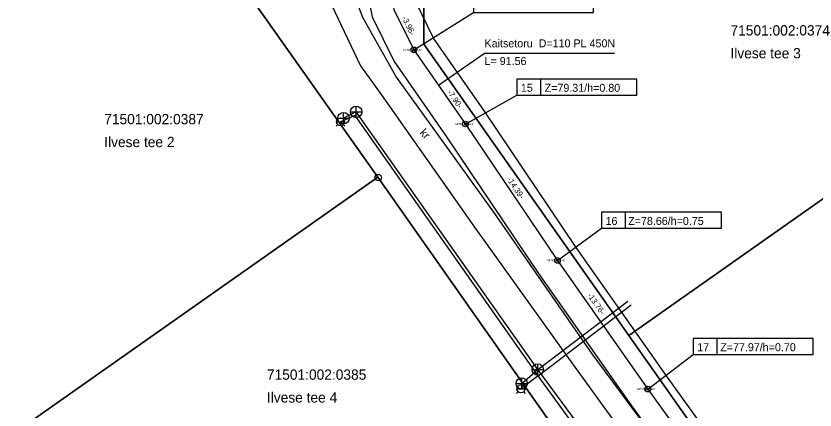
# Model space of a CAD drawing. Extents: x 593727 to 603084, y 6472047 to 6482364.
# Drawn here: x 595964.2 to 596034.1, y 6474006.5 to 6474041 of the extents above; entities that cross this region are included whole.
import ezdxf

# ---------------------------------------------------------------- set-up
doc = ezdxf.new("R2010")
doc.units = 0
for name, color, linetype in [('JOONSIDE', 7, 'Continuous'), ('KKAEV', 7, 'Continuous'), ('KOORDPUNKT', 7, 'Continuous'), ('KTRASS', 7, 'Continuous'), ('MOOTKORG-EH2000', 7, 'Continuous'), ('MOOTMPUNKT', 7, 'Continuous'), ('MOOTNR', 7, 'Continuous'), ('MOOTPIIR', 7, 'Continuous'), ('MPKAABEL', 7, 'Continuous'), ('PIIR', 7, 'Continuous'), ('PIIRIMLEITUD', 7, 'Continuous'), ('TEE', 7, 'Continuous'), ('VKAEV', 7, 'Continuous'), ('VTRASS', 7, 'Continuous')]:
    doc.layers.add(name, color=color, linetype=linetype)

msp = doc.modelspace()

# ---------------------------------------------------------------- linework, layer by layer
at = {"layer": 'KKAEV'}
for p, q in [((595993.91, 6474032.084), (595993.91, 6474033.084)), ((595992.815, 6474031.528), (595992.815, 6474032.528)), ((595993.41, 6474032.584), (595994.41, 6474032.584)), ((595992.315, 6474032.028), (595993.315, 6474032.028)), ((596009.3, 6474010.035), (596010.3, 6474010.035)), ((596009.8, 6474009.535), (596009.8, 6474010.535)), ((596008.4, 6474008.316), (596008.4, 6474009.316)), ((596007.9, 6474008.816), (596008.9, 6474008.816))]:
    msp.add_line(p, q, dxfattribs=at)
for centre in [(595993.91, 6474032.584), (595992.815, 6474032.028), (596009.8, 6474010.035), (596008.4, 6474008.816)]:
    msp.add_circle(centre, 0.5, dxfattribs=at)
at = {"layer": 'KOORDPUNKT'}
for points in [[(595998.968, 6474037.996), (596004.171, 6474041.262), (596014.671, 6474041.262), (596014.671, 6474042.662), (596004.171, 6474042.662), (596004.171, 6474041.262)], [(596003.482, 6474031.514), (596007.973, 6474034.053), (596018.473, 6474034.053), (596018.473, 6474035.453), (596007.973, 6474035.453), (596007.973, 6474034.053)], [(596010.073, 6474034.053), (596010.073, 6474035.453)], [(596011.528, 6474019.578), (596015.367, 6474022.4), (596025.867, 6474022.4), (596025.867, 6474023.8), (596015.367, 6474023.8), (596015.367, 6474022.4)], [(596017.467, 6474022.4), (596017.467, 6474023.8)], [(596019.439, 6474008.315), (596023.402, 6474011.354), (596033.902, 6474011.354), (596033.902, 6474012.754), (596023.402, 6474012.754), (596023.402, 6474011.354)], [(596025.502, 6474011.354), (596025.502, 6474012.754)]]:
    msp.add_lwpolyline(points, dxfattribs=at)
for centre, radius in [((595998.968, 6474037.996), 0.25), ((595998.968, 6474037.996), 0.025), ((595998.968, 6474037.996), 0.0221), ((595998.968, 6474037.996), 0.0191), ((595998.968, 6474037.996), 0.0161), ((595998.968, 6474037.996), 0.0132), ((595998.968, 6474037.996), 0.0102), ((595998.968, 6474037.996), 0.00726), ((595998.968, 6474037.996), 0.0043), ((596003.482, 6474031.514), 0.25), ((596003.482, 6474031.514), 0.025), ((596003.482, 6474031.514), 0.0221), ((596003.482, 6474031.514), 0.0191), ((596003.482, 6474031.514), 0.0161), ((596003.482, 6474031.514), 0.0132), ((596003.482, 6474031.514), 0.0102), ((596003.482, 6474031.514), 0.00726), ((596003.482, 6474031.514), 0.0043), ((596011.528, 6474019.578), 0.25), ((596011.528, 6474019.578), 0.025), ((596011.528, 6474019.578), 0.0221), ((596011.528, 6474019.578), 0.0191), ((596011.528, 6474019.578), 0.0161), ((596011.528, 6474019.578), 0.0132), ((596011.528, 6474019.578), 0.0102), ((596011.528, 6474019.578), 0.00726), ((596011.528, 6474019.578), 0.0043), ((596019.439, 6474008.315), 0.25), ((596019.439, 6474008.315), 0.025), ((596019.439, 6474008.315), 0.0221), ((596019.439, 6474008.315), 0.0191), ((596019.439, 6474008.315), 0.0161), ((596019.439, 6474008.315), 0.0132), ((596019.439, 6474008.315), 0.0102), ((596019.439, 6474008.315), 0.00726), ((596019.439, 6474008.315), 0.0043)]:
    msp.add_circle(centre, radius, dxfattribs=at)
at = {"layer": 'KTRASS'}
for p, q in [((596009.8, 6474010.035), (596017.69, 6474016.021)), ((596008.4, 6474008.816), (596009.8, 6474010.035))]:
    msp.add_line(p, q, dxfattribs=at)
msp.add_lwpolyline([(596021.268, 6473994.477), (596009.8, 6474010.035), (595993.91, 6474032.584), (595992.815, 6474032.028)], dxfattribs=at)
at = {"layer": 'MOOTMPUNKT'}
for centre in [(595998.968, 6474037.996), (596003.482, 6474031.514), (596011.528, 6474019.578), (596019.439, 6474008.315)]:
    msp.add_circle(centre, 0.1, dxfattribs=at)
at = {"layer": 'MOOTPIIR'}
for points in [[(595994.372, 6474045.491), (595995.314, 6474040.897), (595997.24, 6474036.978), (596001.832, 6474030.384), (596009.88, 6474018.444), (596017.808, 6474007.157), (596025.372, 6473996.624)], [(596028.584, 6473999.008), (596021.07, 6474009.473), (596013.176, 6474020.712), (596005.132, 6474032.644), (596000.696, 6474039.014), (595999.13, 6474042.201)]]:
    msp.add_lwpolyline(points, dxfattribs=at)
at = {"layer": 'MPKAABEL'}
for points in [[(596014.463, 6474066.806), (596002.148, 6474057.419), (595998.723, 6474054.604), (595996.671, 6474051.87), (595996.141, 6474049.764), (595996.361, 6474045.748), (595997.222, 6474041.549), (595998.968, 6474037.996), (596003.482, 6474031.514), (596011.528, 6474019.578), (596019.439, 6474008.315), (596026.978, 6473997.816), (596029.342, 6473994.732), (596029.364, 6473993.819)], [(595997.222, 6474041.549), (595998.968, 6474037.996), (596003.482, 6474031.514), (596011.528, 6474019.578), (596019.439, 6474008.315), (596026.978, 6473997.816), (596029.342, 6473994.732), (596029.364, 6473993.819), (596026.896, 6473991.824), (596022.401, 6473988.312), (596009.78, 6473979.811), (596004.261, 6473975.645), (595998.04, 6473970.949), (595995.228, 6473969.033), (595993.808, 6473968.997), (595992.272, 6473970.526), (595991.471, 6473971.588), (595989.417, 6473974.773), (595989.197, 6473975.301)], [(596001.113, 6474034.915), (596005.148, 6474037.725), (596016.522, 6474037.725)]]:
    msp.add_lwpolyline(points, dxfattribs=at)
at = {"layer": 'PIIR'}
for points in [[(596017.77, 6474013.02), (595999.85, 6474038.49), (595999.81, 6474054.43), (596023.26, 6474070.93), (596048.7, 6474034.81)], [(595920.02, 6474021.81), (595923.45, 6474023.94), (595974.94, 6474056.4), (595995.81, 6474026.85), (595965.97, 6474005.85), (595935.81, 6473984.63), (595931.46, 6473994.7)], [(596017.77, 6474013.02), (596048.7, 6474034.81), (596055.18, 6474039.36), (596075.89, 6474009.92), (596066.09, 6474003.01), (596067.53, 6474000.96), (596039.91, 6473981.55)], [(595965.97, 6474005.85), (595995.81, 6474026.85), (596019.09, 6473993.75), (595999.1, 6473979.65), (595997.67, 6473981.68), (595987.85, 6473974.77)]]:
    msp.add_lwpolyline(points, close=True, dxfattribs=at)
for points in [[(596066.57, 6473926.31), (596046.52, 6473955.01), (596023.13, 6473988.02), (596003.14, 6473973.91), (596004.56, 6473971.88), (595994.75, 6473964.97), (595991.31, 6473969.86), (595987.85, 6473974.77), (595997.67, 6473981.68), (595999.1, 6473979.65), (596019.09, 6473993.75), (595995.81, 6474026.85), (595974.94, 6474056.4)], [(595999.81, 6474054.43), (595999.85, 6474038.49), (596017.77, 6474013.02), (596039.91, 6473981.55), (596067.53, 6474000.96), (596066.09, 6474003.01), (596075.89, 6474009.92), (596079.35, 6474005.02), (596082.79, 6474000.11), (596072.98, 6473993.2), (596071.55, 6473995.25), (596043.93, 6473975.83), (596066.1, 6473944.35)]]:
    msp.add_lwpolyline(points, dxfattribs=at)
at = {"layer": 'PIIRIMLEITUD'}
msp.add_circle((595995.847, 6474026.821), 0.285, dxfattribs=at)
at = {"layer": 'TEE'}
for points in [[(596031.92, 6474089.538), (596031.304, 6474086.654), (596029.381, 6474083.691), (596025.099, 6474079.23), (596019.083, 6474074.682), (596007.86, 6474067.339), (595996.337, 6474059.544), (595994.689, 6474057.913), (595992.598, 6474055.095), (595991.286, 6474052.246), (595990.709, 6474049.521), (595990.678, 6474045.813), (595991.744, 6474041.996), (595994.295, 6474036.613), (595996.116, 6474034.095), (596004.269, 6474022.484), (596012.454, 6474011.067), (596021.171, 6473999.009), (596029.659, 6473987.552)], [(596031.256, 6473989.002), (596022.629, 6474000.49), (596014.566, 6474011.418), (596005.949, 6474023.815), (595997.389, 6474035.698), (595994.514, 6474040.842), (595992.998, 6474044.834), (595992.861, 6474048.906), (595993.607, 6474052.227), (595995.052, 6474054.981), (595997.577, 6474057.706), (596008.43, 6474065.294), (596020.365, 6474072.528), (596025.712, 6474076.969), (596031.411, 6474082.45), (596033.754, 6474085.703), (596034.258, 6474088.185)]]:
    msp.add_lwpolyline(points, dxfattribs=at)
at = {"layer": 'VKAEV'}
for p, q in [((595992.197, 6474031.717), (595992.897, 6474031.717)), ((595992.3, 6474031.47), (595992.16, 6474031.33)), ((595992.794, 6474031.47), (595992.934, 6474031.33)), ((596008.079, 6474008.083), (596007.939, 6474007.943)), ((596007.976, 6474008.33), (596008.676, 6474008.33)), ((596008.573, 6474008.083), (596008.713, 6474007.943))]:
    msp.add_line(p, q, dxfattribs=at)
for centre in [(595992.547, 6474031.717), (596008.326, 6474008.33)]:
    msp.add_circle(centre, 0.35, dxfattribs=at)
at = {"layer": 'VTRASS'}
msp.add_line((596009.847, 6474009.478), (596017.976, 6474015.699), dxfattribs=at)
for points in [[(596009.847, 6474009.478), (595993.822, 6474032.26), (595992.547, 6474031.717)], [(596021.07, 6473993.982), (596009.847, 6474009.478), (596008.326, 6474008.33)]]:
    msp.add_lwpolyline(points, dxfattribs=at)

# ---------------------------------------------------------------- texts
at = {"layer": 'JOONSIDE'}
for s, rotation, p in [('-3.96-', 296.17023, (595997.901, 6474040.791)), ('-7.90-', 304.85297, (596001.865, 6474034.277)), ('-14.39-', 303.98372, (596007.076, 6474026.674)), ('-13.76-', 305.08376, (596014.115, 6474016.516))]:
    msp.add_text(s, height=0.5, rotation=rotation, dxfattribs=at).set_placement(p)
at = {"layer": 'KOORDPUNKT'}
for s, p in [('15', (596008.323, 6474034.333)), ('Z=79.31/h=0.80', (596010.406, 6474034.333)), ('16', (596015.735, 6474022.68)), ('Z=78.66/h=0.75', (596017.713, 6474022.68)), ('17', (596023.752, 6474011.634)), ('Z=77.97/h=0.70', (596025.765, 6474011.634))]:
    msp.add_text(s, height=0.7, dxfattribs=at).set_placement(p)
at = {"layer": 'MOOTKORG-EH2000'}
for s, p in [(' 80.42', (595998.968, 6474037.909)), (' 80.11', (596003.482, 6474031.427)), (' 79.41', (596011.528, 6474019.49)), (' 78.67', (596019.439, 6474008.228))]:
    msp.add_text(s, height=0.175, dxfattribs=at).set_placement(p)
at = {"layer": 'MOOTNR'}
for s, p in [('GPS0020 ', (595997.988, 6474037.909)), ('GPS0019 ', (596002.537, 6474031.427)), ('GPS0018 ', (596010.583, 6474019.49)), ('GPS0017 ', (596018.494, 6474008.228))]:
    msp.add_text(s, height=0.175, dxfattribs=at).set_placement(p)
at = {"layer": 'MPKAABEL'}
for s, p in [('Kaitsetoru  D=110 PL 450N', (596005.148, 6474038.225)), ('L= 91.56', (596005.148, 6474036.675))]:
    msp.add_text(s, height=0.7, dxfattribs=at).set_placement(p)
at = {"layer": 'PIIR'}
for s, p in [('71501:002:0374', (596026.662, 6474039.259)), ('Ilvese tee 3', (596026.662, 6474037.259)), ('71501:002:0387', (595971.875, 6474031.492)), ('Ilvese tee 2', (595971.875, 6474029.492)), ('71501:002:0385', (595986.107, 6474009.136)), ('Ilvese tee 4', (595986.107, 6474007.136))]:
    msp.add_text(s, height=0.9, dxfattribs=at).set_placement(p)
at = {"layer": 'TEE'}
msp.add_text('kr', height=0.7, rotation=313.04714, dxfattribs=at).set_placement((595999.428, 6474030.7))

doc.saveas('drawing.dxf')
